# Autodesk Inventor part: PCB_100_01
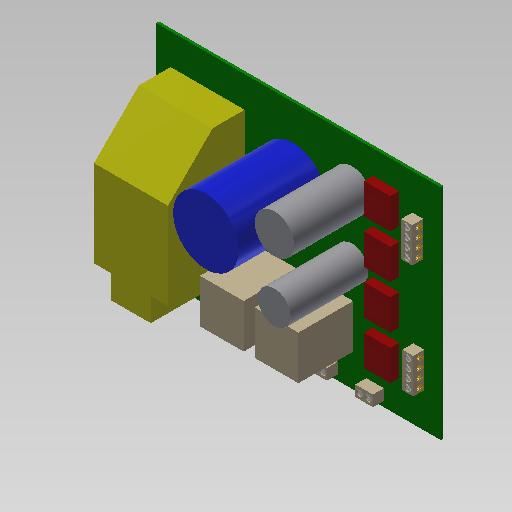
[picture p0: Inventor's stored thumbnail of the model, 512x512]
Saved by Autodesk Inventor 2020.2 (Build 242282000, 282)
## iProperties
GlobalPropertyList: <PropertyList/>
Manager: www.cadconsulting.pl
Company: Fabian Stasiak CAD Consulting
Created: 2014-09
Part Number: PCB_100_01
Material: Ogólny
Document SubType Name: Modeling
Designer: F.Stasiak
Density: 1 g/cm^3
Appearance: Domyślna
Catalog Web Link: www.expertbooks.pl
Author: F.Stasiak
Subject: Zbiór ćwiczeń. Autodesk Inventor 2020. Kurs Professional
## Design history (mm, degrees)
sketch "Szkic1"
  geometry: L1 (-65, 50)-(65, 50); L2 (65, 50)-(65, -50); L3 (65, -50)-(-65, -50); L4 (-65, -50)-(-65, 50); L5 (-65, 50)-(65, -50); L6 (65, 50)-(-65, -50); 1 further point
  constraints: 12 end point, 2 midpoint, 2 parallel, 1 horizontal, 1 perpendicular
  dimensions: "d0" = 130 distance of L2.end L3.end; "d1" = 100 distance of L1.end L2.end
extrude "Wyciągnięcie proste1" new body sketch "Szkic1" distance "d2" = 1.25; taper "d3" = 0 deg
sketch "Szkic2"
  geometry: L1 (5, -35)-(25, -35); L2 (25, -35)-(25, -15); L3 (25, -15)-(5, -15); L4 (5, -15)-(5, -35); L5 (5, -35)-(25, -15); L6 (25, -35)-(5, -15); L7 (65, -50)-(-65, -50) reference; L8 (65, -50)-(65, 50) reference; 2 further points
  constraints: 12 end point, 2 midpoint, 2 parallel, 1 horizontal, 1 perpendicular
  dimensions: "d4" = 20 distance of L3.end L2.end; "d5" = 20 distance of L2.end L1.end; "d8" = 15 distance between parallel lines of L7 L1; "d9" = 40 distance between parallel lines of L8 L2
extrude "Wyciągnięcie proste2" join sketch "Szkic2" distance "d6" = 25; taper "d7" = 0 deg
sketch "Szkic3"
  geometry: L1 (22.159, -37.55)-(42.159, -37.55); L2 (42.159, -37.55)-(42.159, -17.55); L3 (42.159, -17.55)-(22.159, -17.55); L4 (22.159, -17.55)-(22.159, -37.55); L5 (22.159, -37.55)-(42.159, -17.55); L6 (42.159, -37.55)-(22.159, -17.55); L7 (47.159, -17.55)-(47.159, -37.55) reference; L8 (47.159, -37.55)-(67.159, -37.55) reference; 2 further points
  constraints: 12 end point, 2 midpoint, 2 parallel, 1 collinear, 1 horizontal, 1 perpendicular
  dimensions: "d12" = 20 distance of L3.end L2.end; "d13" = 20 distance of L2.end L1.end; "d17" = 5 distance between parallel lines of L7 L2
extrude "Wyciągnięcie proste3" join sketch "Szkic3" taper "d15" = 0 deg; distance "d16" = 25
sketch "Szkic4"
  geometry: C1 r 15 at (-2.266, 18.902); 1 further point
  constraints: 1 centre point
  dimensions: "d18" = 30 diameter of C1
extrude "Wyciągnięcie proste4" join sketch "Szkic4" distance "d19" = 40; taper "d20" = 0 deg
sketch "Szkic5"
  geometry: L1 (-58.369, 35.866)-(-24.6, 35.866); L2 (-24.6, 35.866)-(-24.6, -24.26) reference; L3 (-24.6, -24.26)-(-32.46, -24.26); L4 (-32.46, -24.26)-(-32.46, -35); L5 (-32.46, -35)-(-50.509, -35); L6 (-50.509, -35)-(-50.509, -24.26); L7 (-50.509, -24.26)-(-58.369, -24.26); L8 (-58.369, -24.26)-(-58.369, 35.866); L9 (-20, -35)-(0, -35) reference; 1 further point
  constraints: 16 end point, 5 perpendicular, 2 collinear, 2 point on line, 1 horizontal, 1 parallel, 1 vertical
extrude "Wyciągnięcie proste5" join sketch "Szkic5" distance "d21" = 35; taper "d22" = 0 deg
chamfer "Faza1" distance "d23" = 20.5; stored, may be unused: second distance "d24" = 2, angle "d25" = 45 deg
sketch "Szkic6"
  geometry: L1 (34, -35)-(46, -35); L2 (46, -35)-(46, -21); L3 (46, -21)-(34, -21); L4 (34, -21)-(34, -35); L5 (34, -35)-(46, -21); L6 (46, -35)-(34, -21); L7 (25, -35)-(25, -15) reference; L8 (5, -35)-(25, -35) reference; 2 further points
  constraints: 12 end point, 2 midpoint, 2 parallel, 1 collinear, 1 horizontal, 1 perpendicular
  dimensions: "d26" = 14 distance of L1.end L2.end; "d27" = 12 distance of L1.start L1.end; "d28" = 9 distance between parallel lines of L7 L4
extrude "Wyciągnięcie proste6" join sketch "Szkic6" distance "d29" = 4; taper "d30" = 0 deg
pattern_linear "Szyk prostokątny1" dims "d33" = 20
sketch "Szkic7"
  geometry: C1 r 7.5 at (24.507, 0); C2 r 9 at (24.507, 29.088); 1 further point
  constraints: 2 centre point
  dimensions: "d34" = 15 diameter of C1; "d35" = 18 diameter of C2
extrude "Wyciągnięcie proste7" join sketch "Szkic7" distance "d36" = 35.5; taper "d37" = 0 deg
derived "Z_02.ipt"
feature "Przesuń bryłę6"
derived "Z_04.ipt"
feature "Przesuń bryłę7"
feature "Przesuń bryłę8"
feature "Przesuń bryłę9"
feature "Przesuń bryłę10"
feature "Przesuń bryłę11"
feature "Utwórz kombinację5"
  node "Bryła6"
  node "Bryła7"
  node "Bryła9"
  node "Bryła8"
  node "Bryła10"
sketch "Szkic36"
  geometry: C1 r 1 at (2, 2.5) reference
node "SL1"
sketch "Szkic37"
  geometry: C1 r 1 at (6, 2.5) reference
node "SL2"
sketch "Szkic38"
  geometry: C1 r 1 at (2, 2.5) reference
node "SL3"
sketch "Szkic39"
  geometry: C1 r 1 at (6, 2.5) reference
node "SL4"
sketch "Szkic40"
  geometry: C1 r 1 at (10, 2.5) reference
node "SL5"
sketch "Szkic41"
  geometry: C1 r 1 at (14, 2.5) reference
node "SL6"
sketch "Szkic42"
  geometry: C1 r 1 at (2, 2.5) reference
node "SL7"
sketch "Szkic43"
  geometry: C1 r 1 at (6, 2.5) reference
node "SL8"
sketch "Szkic44"
  geometry: C1 r 1 at (-2.5, 2) reference
node "SR1"
sketch "Szkic45"
  geometry: C1 r 1 at (-2.5, 6) reference
node "SR2"
sketch "Szkic46"
  geometry: C1 r 1 at (-2.5, 10) reference
node "SR3"
sketch "Szkic47"
  geometry: C1 r 1 at (-2.5, 14) reference
node "SR4"
sketch "Szkic48"
  geometry: C1 r 1 at (-2.5, 2) reference
node "SR5"
sketch "Szkic49"
  geometry: C1 r 1 at (-2.5, 6) reference
node "SR6"
sketch "Szkic50"
  geometry: C1 r 1 at (-2.5, 10) reference
node "SR7"
sketch "Szkic51"
  geometry: C1 r 1 at (-2.5, 14) reference
node "SR8"
node "Bryła1"
feature "Bryła1::Z_02.ipt" dims "d79" = 10
tag "Bryła wyprowadzona5"
feature "Bryła1::Z_04.ipt" dims "d83" = 10
tag "Bryła wyprowadzona6"
feature "Bryła1::Z_04.ipt_1" dims "d90" = 10
tag "Bryła wyprowadzona7"
feature "Bryła1::Z_02.ipt_1" dims "d101" = 10
tag "Bryła wyprowadzona8"
feature "Bryła1::Z_04.ipt_2" dims "d105" = 10
tag "Bryła wyprowadzona9"
other parameters: "d81" = -45, "d82" = 1.25, "d85" = -45, "d86" = 1.25, "d91" = -90 deg, "d94" = 1.25, "d95" = -1, "d96" = 0, "d97" = 0, "d102" = 35, "d103" = -45, "d104" = 1.25, "d106" = 90 deg, "d107" = 65, "d109" = 1.25
